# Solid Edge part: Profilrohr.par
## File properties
Username: bmolnar
Dokumentum tartalom típus: 0
Author: bmolnar
Last saved by: bmolnar
Revision: 90
Sűrűség: 0,000 kg/m^3
Pontosság: 0,990
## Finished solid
Body 1: solid body, 115 faces, 338 edges, 224 vertices.
  Faces by surface: cylinder 59, plane 56
  Edges by curve: line 220, circle 118
Bounding box of the edges (mm): 113.500 x 113.500 x 153.000, from (-56.75, -56.75, -136.5) to (56.75, 56.75, 16.5).
Cylindrical faces by radius (mm): R0.15 x24, R0.25 x24, R1 x4, R12.25 x4, R35 x2, R50 x1
Planar faces by outward normal: +x 13, +y 14, +z 1, -x 13, -y 14, -z 1
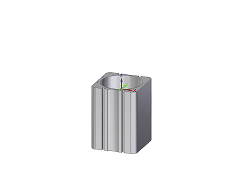
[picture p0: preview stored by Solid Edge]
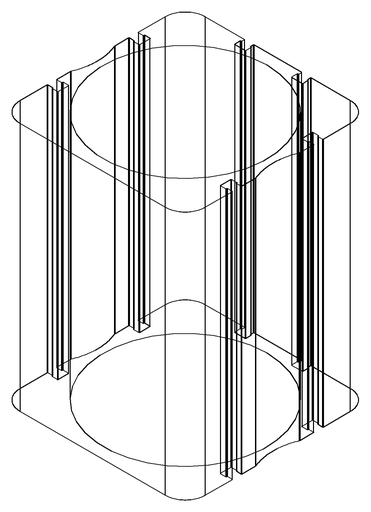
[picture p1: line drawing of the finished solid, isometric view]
